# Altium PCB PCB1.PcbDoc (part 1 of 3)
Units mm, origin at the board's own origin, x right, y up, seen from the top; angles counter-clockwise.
Board outline 131.32 x 71.5 mm, 4 copper layers (Top Layer, Layer 1, Layer 2, Bottom Layer), stack 0.603 mm thick; 122 components, 132 nets, 671 pads, 444 vias.
Unrouted connection lines stored in the file: 1.
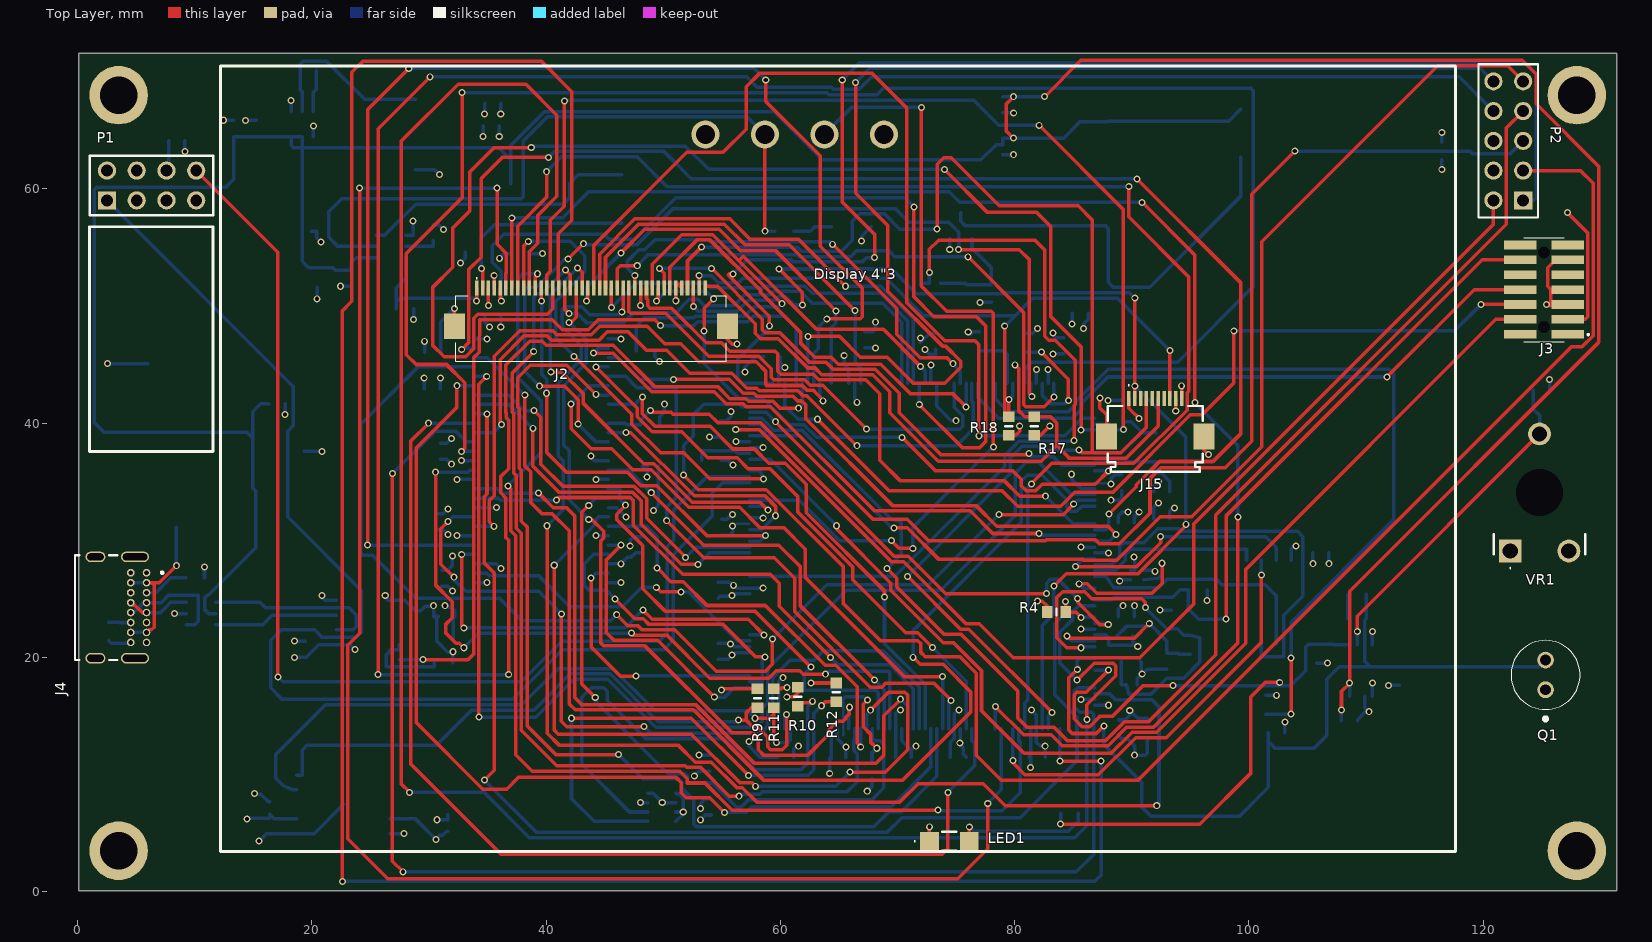
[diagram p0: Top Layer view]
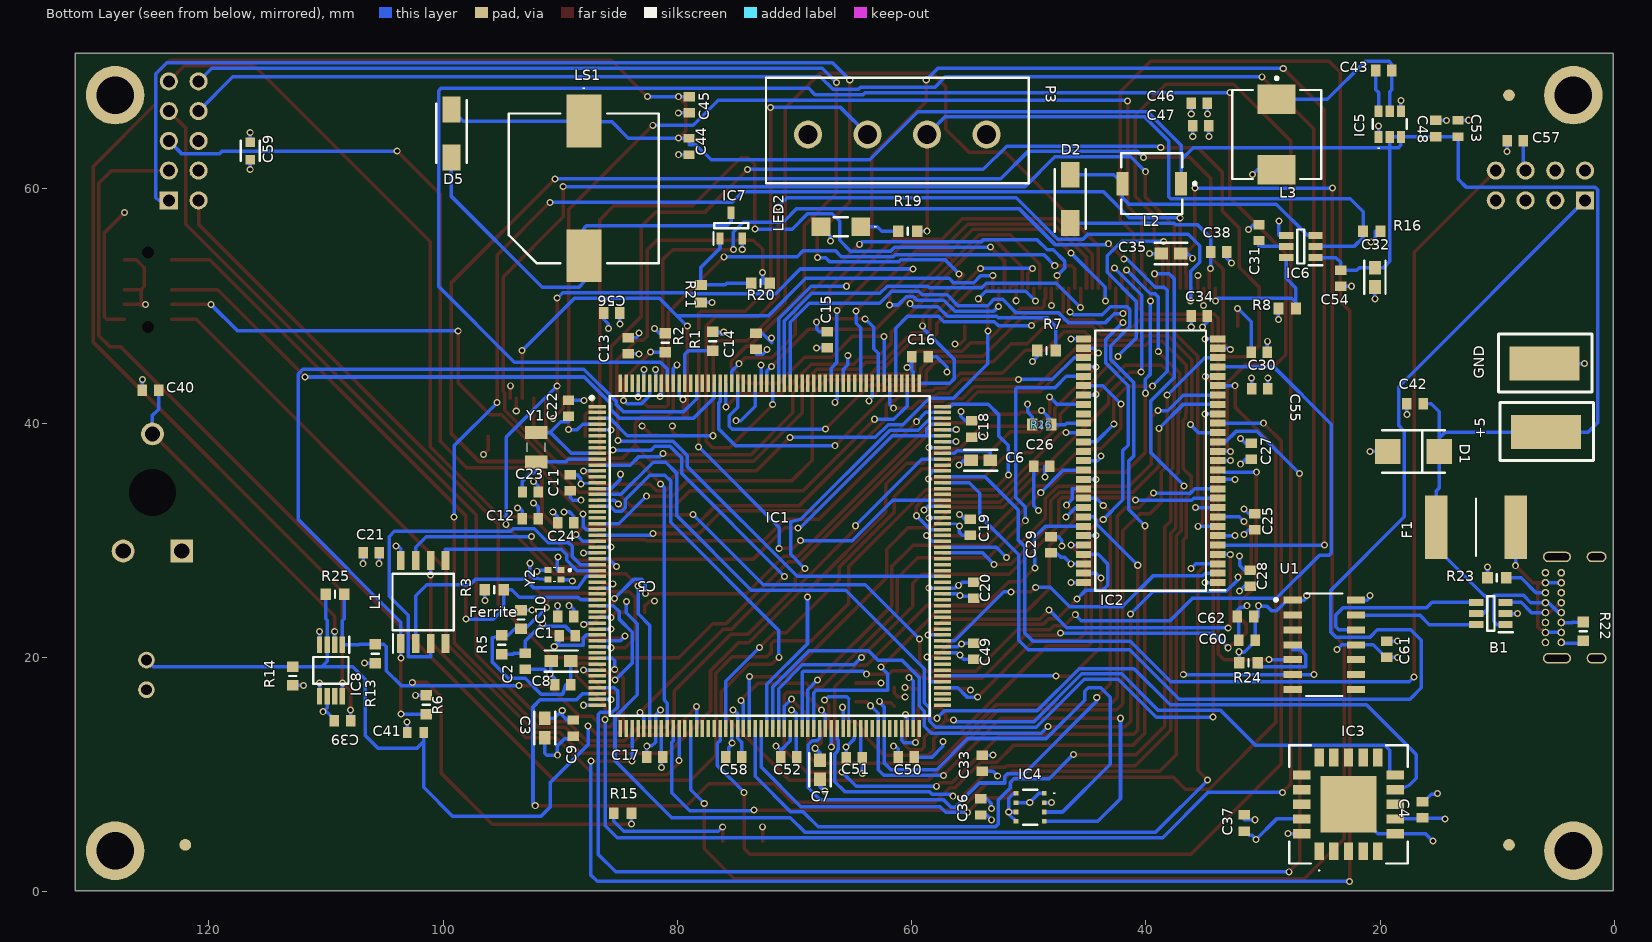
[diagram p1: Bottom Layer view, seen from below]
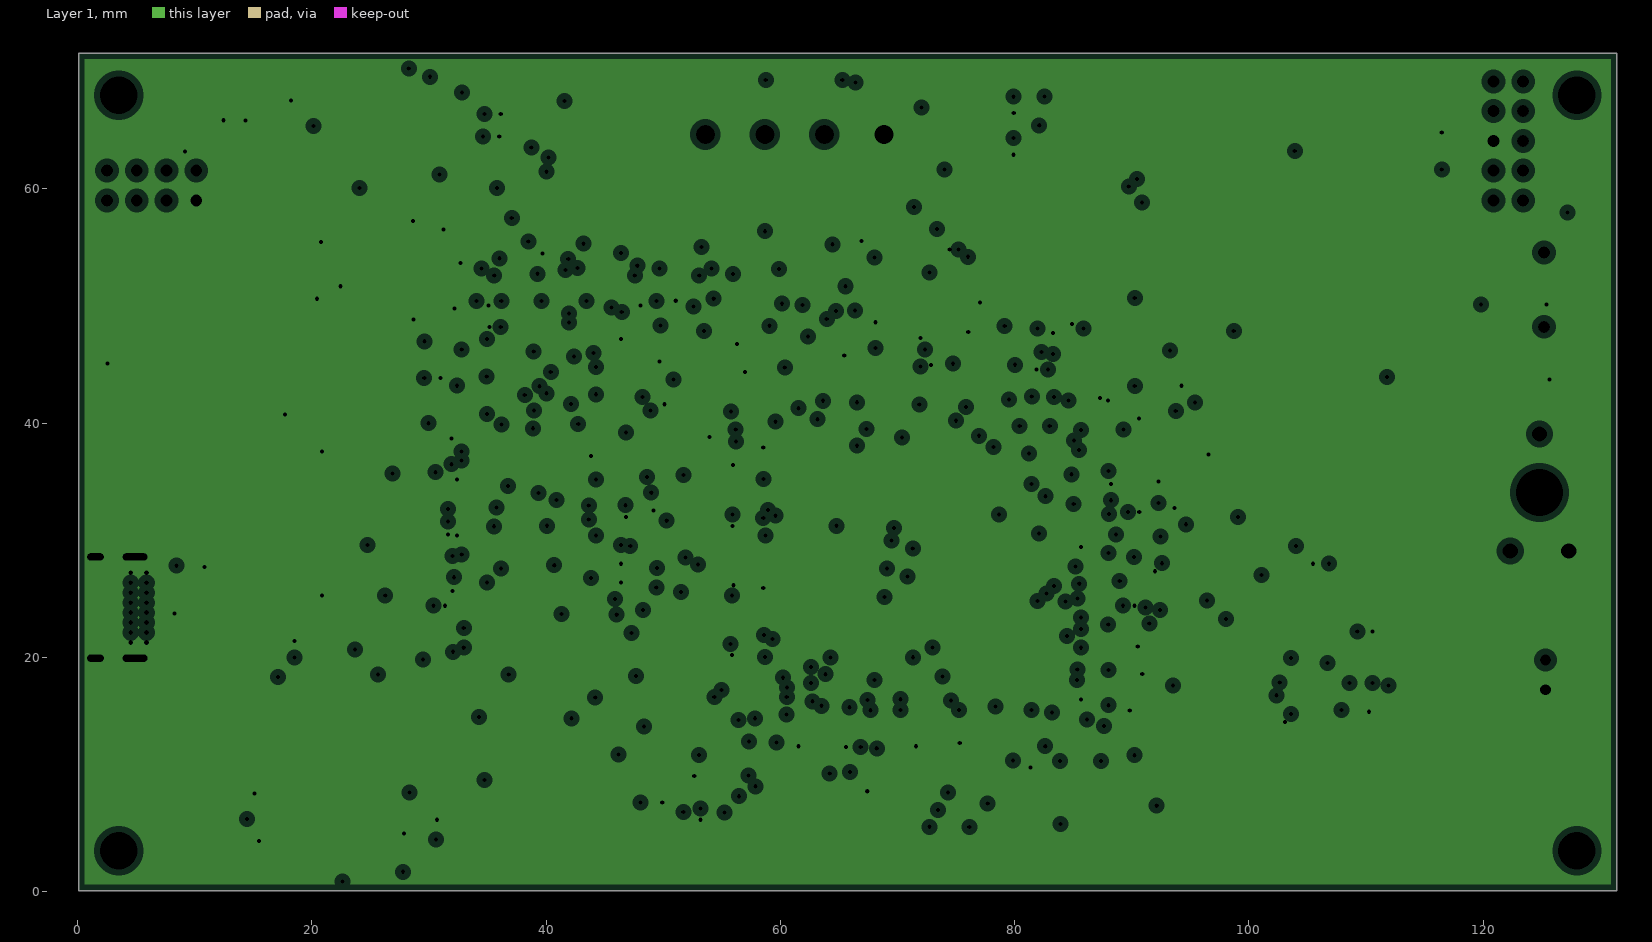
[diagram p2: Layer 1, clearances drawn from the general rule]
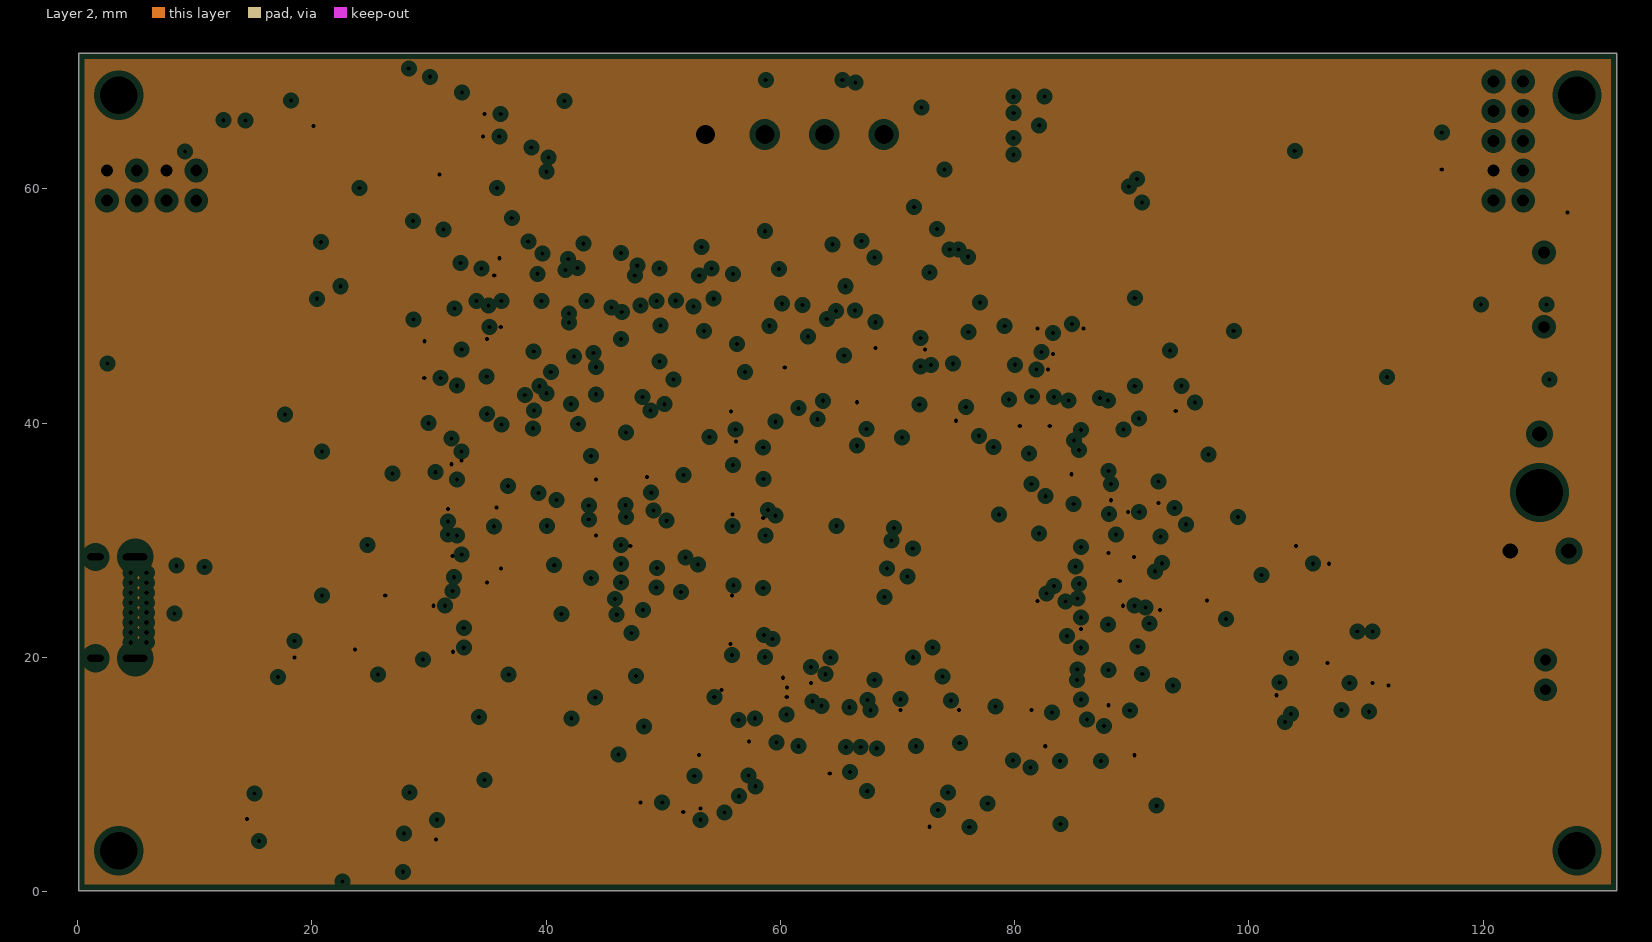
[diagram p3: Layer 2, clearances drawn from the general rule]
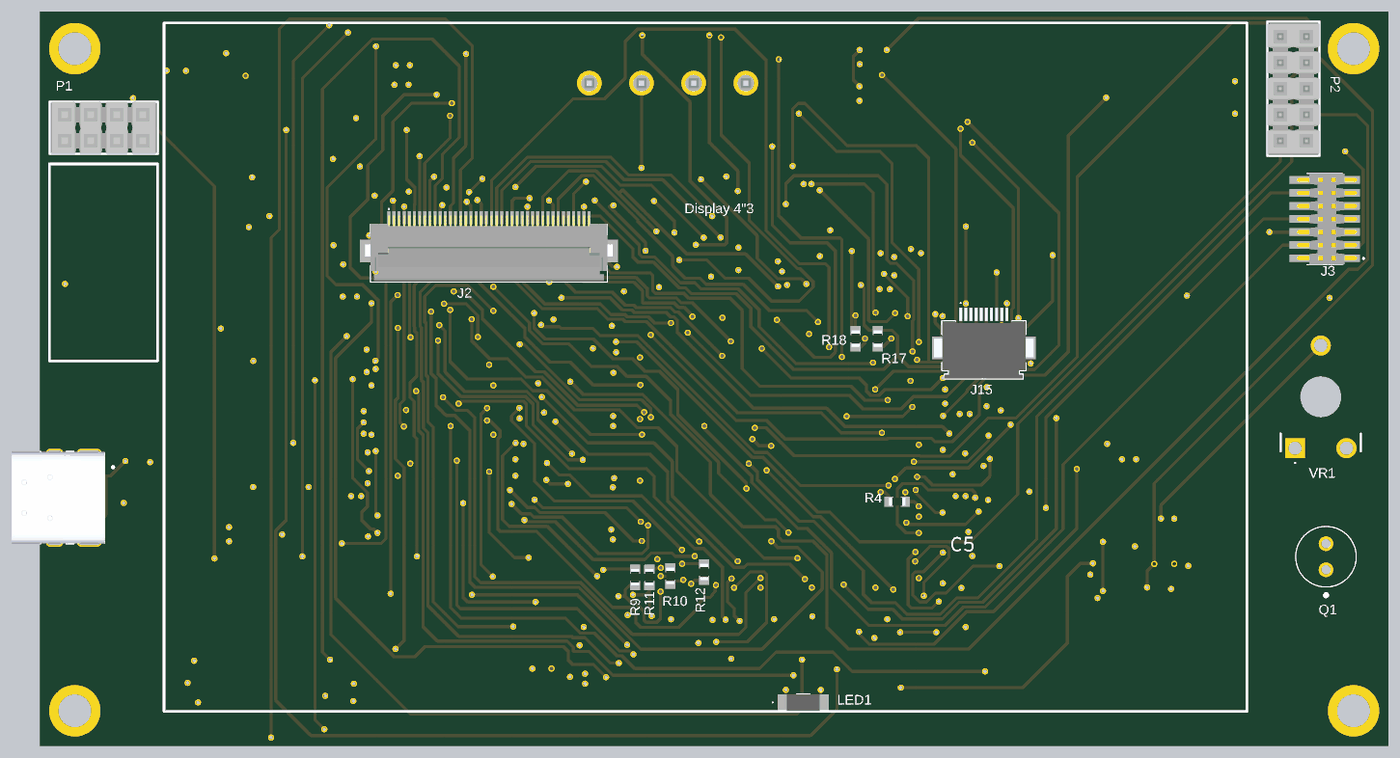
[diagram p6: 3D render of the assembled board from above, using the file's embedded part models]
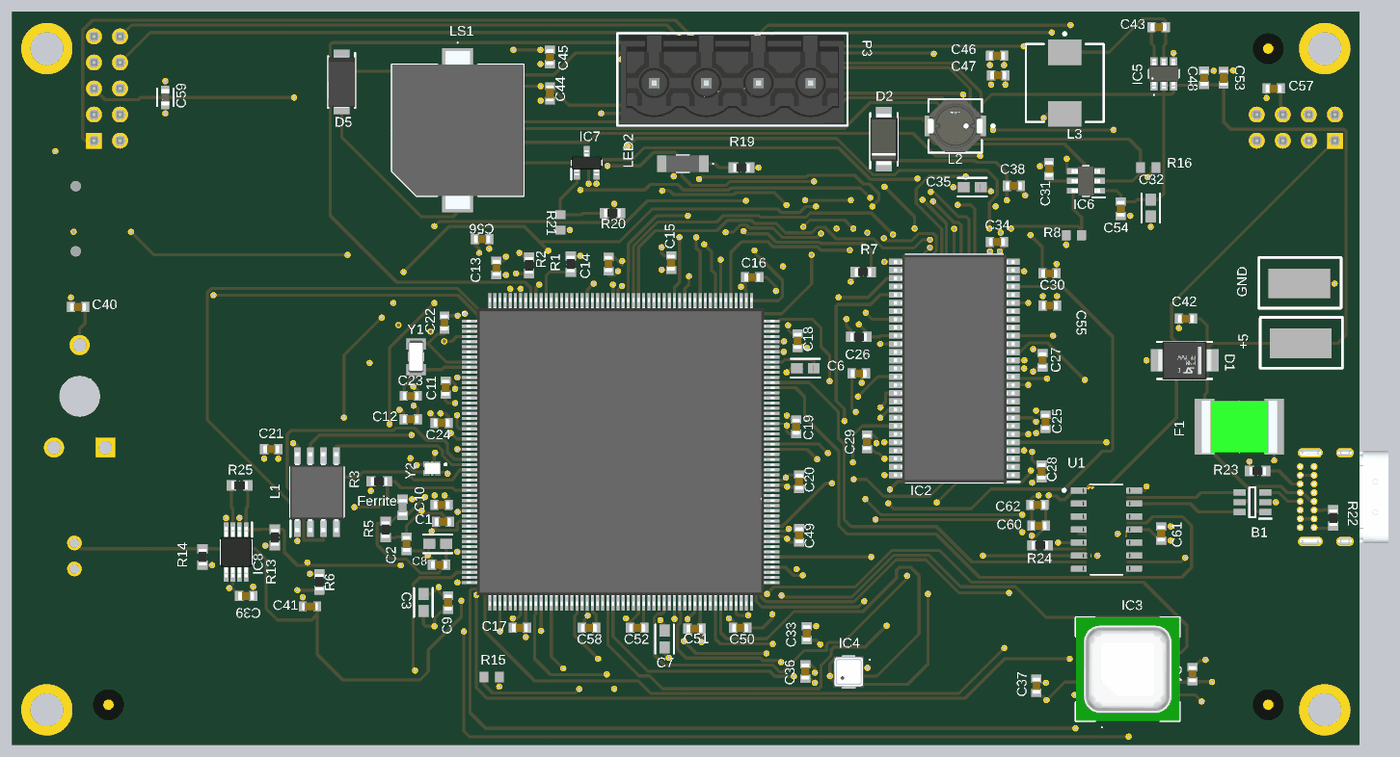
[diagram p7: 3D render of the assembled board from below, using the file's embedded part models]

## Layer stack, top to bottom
Top Solder: solder mask 0.0102, Solder Resist, Dk 3.5
Top Layer: signal copper 0.0356
Dielectric 2: prepreg 0.0711, PP-006, Dk 4.1
Layer 1: plane copper 0.035, net GND
Dielectric 1: dielectric 0.32, FR-4, Dk 4.8
Layer 2: plane copper 0.035, net 3V3
Dielectric 3: prepreg 0.0711, PP-006, Dk 4.1
Bottom Layer: signal copper 0.0356
Bottom Solder: solder mask 0.0102, Solder Resist, Dk 3.5

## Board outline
0.094,0.094 0.094,71.595 131.412,71.595 131.412,0.094

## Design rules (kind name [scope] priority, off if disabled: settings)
Clearance Clearance_OLTTTPPP [OnOutside] p1: gap=0.15 ignorepadtopadclearanceinfootprint=TRUE
Clearance Clearance_ILTTTPPP [All] p2: gap=0.15 ignorepadtopadclearanceinfootprint=TRUE except(0.2: Arc-Hole Track-Hole SMDPad-Hole THPad-Hole Via-Hole Fill-Hole Poly-Hole Region-Hole)
HoleSize [All] p1: absolutevalues=TRUE maxlimit=1000 minlimit=0.25 maxpercent=80.000 minpercent=20.000
HoleToHoleClearance HoleToHoleClearance_uVia_same_layer_inner [IsMicroVia and ((StartLayer = 'Inner 1') and (StopLayer = 'Inner 2')) vs IsMicroVia and ((StartLayer = 'Inner 1') and (StopLayer = 'Inner 2'))] p1: gap=0.2 allowstackedmicrovias=FALSE
HoleToHoleClearance HoleToHoleClearance_uVia_same_layer_top [IsMicroVia and ((StartLayer = 'Top Layer') and (StopLayer = 'Inner 1')) vs IsMicroVia and ((StartLayer = 'Top Layer') and (StopLayer = 'Inner 1'))] p2: gap=0.2 allowstackedmicrovias=FALSE
HoleToHoleClearance HoleToHoleClearance_uVia [IsMicroVia vs IsMicroVia] p3: gap=0.01 allowstackedmicrovias=FALSE
HoleToHoleClearance [All] p4: gap=0.2 allowstackedmicrovias=FALSE
MinimumAnnularRing MinimumAnnularRing_uVia [IsMicroVia] p1: minimumring=0.09
MinimumAnnularRing MinimumAnnularRing_OAR [OnOutside] p2: minimumring=0.125
MinimumAnnularRing MinimumAnnularRing_IAR [All] p3: minimumring=0.125
MinimumSolderMaskSliver [All] p1: minsoldermaskwidth=0.1
PlaneClearance [All] p1: clearance=0.508
PlaneConnect J4_GND_Direct [IsPad And InComponent('J4') And InNet('GND')] p1: planeconnectstyle=Direct reliefexpansion=0.508 reliefentries=4 reliefconductorwidth=0.254 reliefairgap=0.254
PlaneConnect [All] p2: planeconnectstyle=Relief reliefexpansion=0.508 reliefentries=4 reliefconductorwidth=0.254 reliefairgap=0.254
PolygonConnect [All] p1: connectstyle=Relief reliefconductorwidth=0.254 reliefentries=4 polygonreliefangle="90 Angle" airgapwidth=0.254
RoutingVias RoutingVias_uVia [IsMicroVia] p1: holewidth=0.1 width=0.28 viastyle="Through Hole" minholewidth=0.1 minwidth=0.28 maxholewidth=0.1 maxwidth=0.28
RoutingVias [All] p2: holewidth=0.35 width=0.6 viastyle="Through Hole" minholewidth=0.25 minwidth=0.5 maxholewidth=3 maxwidth=3.25
SilkToSolderMaskClearance [IsPad] p1: minsilkscreentomaskgap=0.15 clearancetoexposedcopper=TRUE
SolderMaskExpansion [All] p1: expansion=0 istentingtop=FALSE
SupplyNets "Schematic Supply Nets_4" [InNet('3V3')] p1: voltage=0.000
SupplyNets "Schematic Supply Nets_3" [InNet('+5')] p2: voltage=0.000
SupplyNets "Schematic Supply Nets_2" [InNet('VREF+')] p3: voltage=0.000
SupplyNets "Schematic Supply Nets_1" [InNet('VDDA')] p4: voltage=0.000
SupplyNets "Schematic Supply Nets" [InNet('GND')] p5: voltage=0.000
ViasUnderSMD [IsMicroVia] p1: allowed=TRUE
Width Width_ILTW [All] p1: maxlimit=3 minlimit=0.2 preferedwidth=0.3 minimp=50.000000 maximp=50.000000 favimp=50.000000
Width POWER [InNet('+5')] p2: maxlimit=3 minlimit=0.2 preferedwidth=0.5 minimp=50.000000 maximp=50.000000 favimp=50.000000
Width POWER_1 [InNet('3V3')] p3: maxlimit=3 minlimit=0.2 preferedwidth=0.5 minimp=50.000000 maximp=50.000000 favimp=50.000000
Width POWER_2 [InNet('GND')] p4: maxlimit=3 minlimit=0.2 preferedwidth=0.5 minimp=50.000000 maximp=50.000000 favimp=50.000000
24 further rules are at their usual default settings.

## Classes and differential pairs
component class Sheet2: +5 B1 C34 C42 C43 C46 C47 C48 C53 C60 C61 C62 D1 F1 GND IC5 J3 J4 L3 R22 R23 R24 U1
net class LCD_R[0..7]: LCD_R0 LCD_R1 LCD_R2 LCD_R3 LCD_R4 LCD_R5 LCD_R6 LCD_R7
net class LCD_G[0..7]: LCD_G0 LCD_G1 LCD_G2 LCD_G3 LCD_G4 LCD_G5 LCD_G6 LCD_G7
net class LCD_B[0..7]: LCD_B0 LCD_B1 LCD_B2 LCD_B3 LCD_B4 LCD_B5 LCD_B6 LCD_B7
net class SDRAM_D[0..15]: SDRAM_D0 SDRAM_D1 SDRAM_D2 SDRAM_D3 SDRAM_D4 SDRAM_D5 SDRAM_D6 SDRAM_D7 SDRAM_D8 SDRAM_D9 SDRAM_D10 SDRAM_D11 SDRAM_D12 SDRAM_D13 SDRAM_D14 SDRAM_D15
net class SDRAM_A[0..11]: SDRAM_A0 SDRAM_A1 SDRAM_A2 SDRAM_A3 SDRAM_A4 SDRAM_A5 SDRAM_A6 SDRAM_A7 SDRAM_A8 SDRAM_A9 SDRAM_A10 SDRAM_A11
component class Sheet6: C21 C22 C23 C24 C25 C26 C27 C28 C29 C30 C55 C57 C59 IC2 L1 P1 P2 R4 R6 R26 Y1 Y2
component class Sheet5: C31 C32 C35 C38 C54 C56 D2 IC6 J2 J15 L2 LED2 P3 R7 R8 R16 R17 R18 R19
component class Sheet3: C1 C2 C3 C5 C6 C7 C8 C9 C10 C11 C12 C13 C14 C15 C16 C17 C18 C19 C20 C49 C50 C51 C52 C58 Ferrite R5
component class Sheet4: C4 C33 C36 C37 C39 C40 C41 C44 C45 D5 IC3 IC4 IC7 IC8 LED1 LS1 Q1 R9 R10 R11 R12 R13 R14 R15 R20 R21 R25 VR1
component class Sheet1: IC1 R1 R2 R3

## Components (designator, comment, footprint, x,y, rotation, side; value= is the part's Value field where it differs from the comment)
+5 "1" ANT 6.096,39.624 r270 bottom
B1 "USBLC6-2SC6" SOT95P280X145-6N 10.541,23.749 r0 bottom
C1 "1uf" CAPC1608X95N 89.408,21.844 r180 bottom
C2 "100nf" CAPC1608X95N 92.964,19.685 r90 bottom
C3 "4.7uf" FP-CL10-IPC_A 91.313,13.97 r90 bottom
C4 "10Uf" CAPC1608X95N 16.383,6.985 r270 bottom
C5 "1UF" FP-CL10-IPC_A 89.916,19.685 r0 bottom
C6 "2.2uf" FP-CL10-IPC_A 54.102,36.83 r0 bottom
C7 "2.2uf" FP-CL10-IPC_A 67.818,10.414 r270 bottom
C8 "100nf" CAPC1608X95N 89.789,17.653 r180 bottom
C9 "100nf" CAPC1608X95N 88.9,13.97 r270 bottom
C10 "100nf" CAPC1608X95N 89.535,23.495 r180 bottom
C11 "100nf" CAPC1608X95N 89.154,34.925 r270 bottom
C12 "100nf" CAPC1608X95N 92.55,31.844 r180 bottom
C13 "100nf" CAPC1608X95N 84.201,46.609 r270 bottom
C14 "100nf" CAPC1608X95N 73.279,46.99 r270 bottom
C15 "100nf" CAPC1608X95N 67.183,47.117 r270 bottom
C16 "100nf" CAPC1608X95N 59.276,45.687 r0 bottom
C17 "100nf" CAPC1608X95N 81.915,11.5 r0 bottom
C18 "100nf" CAPC1608X95N 54.864,39.497 r90 bottom
C19 "100nf" CAPC1608X95N 54.991,31.115 r90 bottom
C20 "100nf" CAPC1608X95N 54.704,25.748 r270 bottom
C21 "100nf" CAPC1608X95N 106.139,28.923 r0 bottom
C22 "18pf" CAPC1608X87N 89.281,41.275 r270 bottom
C23 "18pf" CAPC1608X87N 92.55,34.13 r0 bottom
C24 "100nf" CAPC1608X95N 89.535,31.496 r180 bottom
C25 "100nf" CAPC1608X95N 30.701,31.59 r90 bottom
C26 "100nf" CAPC1608X95N 48.895,36.322 r180 bottom
C27 "100nf" CAPC1608X95N 30.988,37.592 r270 bottom
C28 "100nf" CAPC1608X95N 31.082,26.764 r90 bottom
C29 "100nf" CAPC1608X95N 48.1,29.634 r90 bottom
C30 "100nf" CAPC1608X95N 30.32,46.068 r180 bottom
C31 "220nF" CAPC1608X87N 30.353,56.261 r270 bottom
C32 "4.7uf" FP-CL10-IPC_A 20.447,52.451 r270 bottom
C33 "100nf" CAPC1608X95N 53.975,10.977 r90 bottom
C34 "100nf" CAPC1608X95N 35.433,49.149 r0 bottom
C35 "4.7uf" FP-CL10-IPC_A 37.846,54.483 r0 bottom
C36 "100nf" CAPC1608X95N 54.102,7.239 r90 bottom
C37 "100nf" CAPC1608X95N 31.59,5.86 r270 bottom
C38 "4.7uf" CAPC1608X95N 33.782,54.61 r0 bottom
C39 "100nf" CAPC1608X95N 108.585,14.605 r180 bottom
C40 "100nf" CAPC1608X95N 124.968,42.799 r180 bottom
C41 "0.47uf" CAPC1608X90N 102.362,13.589 r180 bottom
C42 "100nf" CAPC1608X95N 17.018,41.656 r180 bottom
C43 "100nf" CAPC1608X95N 19.685,70.104 r0 bottom
C44 "10uf" CAPC1608X90N 78.994,63.627 r90 bottom
C45 "100nf" CAPC1608X95N 78.994,67.183 r90 bottom
C46 "22uf" CAPC1608X95N 35.433,67.31 r180 bottom
C47 "22uf" CAPC1608X95N 35.306,65.405 r180 bottom
C48 "100nf" CAPC1608X95N 15.24,65.151 r270 bottom
C49 "100nf" CAPC1608X95N 54.704,20.541 r90 bottom
C50 "100nf" CAPC1608X95N 60.452,11.5 r180 bottom
C51 "100nf" CAPC1608X95N 64.897,11.43 r180 bottom
C52 "100nf" CAPC1608X95N 70.485,11.5 r180 bottom
C53 "10UF" CAPC1608X90N 13.335,65.151 r270 bottom
C54 "100nf" CAPC1608X95N 23.368,52.379 r90 bottom
C55 "4.7uf" CAPC1608X95N 30.281,42.926 r180 bottom
C56 "100nf" CAPC1608X95N 85.598,49.403 r0 bottom
C57 "100nf" CAPC1608X95N 8.476,64.102 r0 bottom
C58 "100nf" CAPC1608X95N 75.184,11.5 r180 bottom
C59 "100nf" FP-VJ0603X-MFG 116.459,63.246 r90 bottom
C60 "100nf" CAPC1608X95N 31.369,21.463 r180 bottom
C61 "330nf" CAPC1608X95N 19.431,20.701 r270 bottom
C62 "100nf" CAPC1608X95N 31.496,23.495 r180 bottom
D1 "SMBJ5.0A" SMBJ12A 17.145,37.592 r0 bottom
D2 "SS16-E3_61T" DIOM5127X229N 46.449,59.149 r90 bottom
D5 "SS14" DIOM5026X262N 99.281,64.737 r270 bottom
F1 "0ZCF0300BF2C" FUSC7451X115N 11.811,31.115 r0 bottom
Ferrite "FCM1608KF-601T03" BEADC1608X95N 93.345,23.241 r270 bottom (schematic designator "Ferrite Chip Bead")
GND "1" ANT 6.223,45.466 r270 bottom
IC1 "STM32F746BGT6" QFP50P3000X3000X160-208N 72.103,28.669 r180 bottom
IC2 "IS42S16400J-7TLI" SOP80P1176X120-54N 39.591,36.797 r0 bottom
IC3 "SCD41-D-R1" SCD41DR1 22.7,7.46 r90 bottom
IC4 "BME688" BME688 49.878,7.206 r180 bottom
IC5 "AP63203WU-7" AP63203WU7 19.177,65.532 r180 bottom
IC6 "TPS61165DBVT" SOT95P280X145-6N 26.764,55.085 r0 bottom
IC7 "2N7002P,235" SOT95P230X110-3N 75.405,56.863 r90 bottom
IC8 "LMV393MM_NOPB" SOP65P490X110-8N 109.568,18.89 r270 bottom
J2 "FH12-40S-0.5SH_55_" FH1240S05SH55 43.817,48.854 r0 top
J3 "FTSH-107-01-L-DV-K-A" FTSH-107-XX-YYY-DV-K-A 125.186,51.402 r90 top
J4 "USB4085-GF-A_REVA4" GCT_USB4085-GF-A_REVA4 1.524,24.257 r270 top
J15 "FH12-10S-0.5SH_55_" FH1210S05SH55 92,38.989 r0 top
L1 "W25Q128JVSIQ_TR" SOIC127P780X195-8N 101.694,24.732 r90 bottom
L2 "#A915AY-100M=P3" FP-D53LC-MFG 39.497,60.452 r0 bottom
L3 "DR74-4R7-R" COBU-DR74-4R7-R_V 28.829,64.643 r270 bottom
LED1 "KPTL-3216SURCK-01-VS" KPTL3216SURCK01VS 74.422,4.318 r0 top
LED2 "KPTL-3216SURCK-01-VS" KPTL3216SURCK01VS 66.04,56.769 r0 bottom
LS1 "SMI-1324-TW-5V-3-R" SMI1324TW5V3R 87.978,60.038 r90 bottom
P1 "ESP-01" SMTC-MTSW-104-12-X-D-006 2.507,59.022 r0 top
P2 "TSW-105-05-G-D" SMTC-TSW-105-05-X-D 123.411,59.022 r90 top
P3 "691701510004B" 691701510004B 61.214,64.993 r180 bottom
Q1 "PT334-6B" PT3346B 125.316,17.239 r90 top
R1 "10k" RESC1608X55N 76.962,46.99 r90 bottom
R2 "10k" RESC1608X55N 81.026,46.863 r270 bottom
R3 "10k" RESC1608X55N 95.631,25.781 r0 bottom
R4 "10k" RESC1608X55N 83.566,23.876 r0 top
R5 "47" RESC1608X55N 94.996,21.082 r90 bottom
R6 "10k" RESC1608X55N 101.44,15.969 r270 bottom
R7 "4k7" RESC1608X55N 48.481,46.195 r180 bottom
R8 "10 OHM" RESC1608X50N 27.94,49.784 r180 bottom
R9 "4k7" RESC1608X55N 58.039,16.51 r90 top
R10 "4k7" RESC1608X55N 61.468,16.637 r90 top
R11 "4k7" RESC1608X55N 59.436,16.51 r270 top
R12 "4k7" RESC1608X55N 64.77,17.018 r270 top
R13 "10k" RESC1608X55N 105.791,20.32 r90 bottom
R14 "10k" RESC1608X55N 112.838,18.415 r90 bottom
R15 "1k" RESC1608X50N 84.676,6.698 r0 bottom
R16 "100k" RESC1608X50N 20.701,56.388 r180 bottom
R17 "4k7" RESC1608X55N 81.661,39.751 r270 top
R18 "4k7" RESC1608X55N 79.502,39.751 r270 top
R19 "4k7" RESC1608X55N 60.325,56.388 r180 bottom
R20 "100 OHM" RESC1608X55N 72.898,51.943 r0 bottom
R21 "10K" RESC1608X50N 77.978,51.054 r90 bottom
R22 "5.1 kΩ, 1%" RESC1608X55N 2.667,22.225 r90 bottom
R23 "5.1 kΩ, 1%" RESC1608X55N 10.033,26.797 r180 bottom
R24 "10K" RESC1608X55N 31.242,19.558 r180 bottom
R25 "1M" RESC1608X55N 109.22,25.4 r0 bottom
R26 "10k" RESC1608X55N 48.895,39.878 r180 bottom
U1 "MCP2221A-I/SL" FP-C04-065-SL-MFG 24.765,21.082 r180 bottom
VR1 "PT10MV11-104A2020-S" PT10MV11104A2020S 122.308,29.083 r0 top
Y1 "ABS07-32.768KHZ-T" ABS07 92.042,37.94 r270 bottom
Y2 "ASCO-8.000MHZ-EK-T3" ASCO16000MHZEKT 90.17,27.051 r0 bottom

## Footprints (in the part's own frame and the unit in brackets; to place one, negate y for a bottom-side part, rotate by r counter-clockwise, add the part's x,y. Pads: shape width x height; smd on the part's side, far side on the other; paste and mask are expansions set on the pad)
691701510004B [mm] "THR - 5,08mm - PCB Vertical Close - 04p"
  round 2.4 hole 1.6: 1(-7.62,-0.35) 2(-2.54,-0.35) 3(2.54,-0.35) 4(7.62,-0.35)
  silkscreen extent -11.21,-4.5 11.21,4.5, body extent -10.86,-4.25 10.86,4.25, height 12.1
ABS07 [mm]
  rect 1.1x1.9 smd: 1(-1.25,0) 2(1.25,0)
  silkscreen extent -0.4,-0.75 0.4,0.75, body extent -1.6,-0.75 1.6,0.75, height 0.9
ANT [mm]
  rect 2.88x6 smd: 1(0.381,0.254)
  silkscreen extent -2.16,-3.68 2.79,4.32
AP63203WU7 [mm]
  rect 0.7x1 smd: 1(-0.95,-1.099) 2(0,-1.099) 3(0.95,-1.099) 4(0.95,1.099) 5(0,1.099) 6(-0.95,1.099)
  silkscreen extent -1.45,-2.1 1.45,0.4, body extent -1.45,-1.45 1.45,1.45, height 1
ASCO16000MHZEKT [mm]
  rect 0.6x0.5 smd: 1(-0.25,-0.4) 2(0.85,-0.4) 3(0.85,0.4) 4(-0.25,0.4)
  silkscreen extent -1.1,-0.6 0.4,0.6, body extent -0.52,-0.6 1.08,0.6, height 0.7
BEADC1608X95N [mm]
  rect 0.9x1 smd: 1(-0.8,0) 2(0.8,0)
  silkscreen extent 0,-0.3 0,0.3, body extent -0.8,-0.4 0.8,0.4, height 0.95
BME688 [mm]
  rect 0.4x0.4 smd: 1(1.2,1.2) 2(1.2,0.4) 3(1.2,-0.4) 4(1.2,-1.2) 5(-1.2,-1.2) 6(-1.2,-0.4) 7(-1.2,0.4) 8(-1.2,1.2)
  silkscreen extent -0.6,-1.5 2.1,1.5, body extent -1.5,-1.5 1.5,1.5, height 0.93
CAPC1608X87N [mm]
  rect 0.8x0.94 smd: 1(-0.67,0) 2(0.67,0)
  body extent -0.8,-0.4 0.8,0.4, height 0.87
CAPC1608X90N [mm]
  rect 0.73x0.94 smd: 1(-0.71,0) 2(0.71,0)
  body extent -0.8,-0.4 0.8,0.4, height 0.9
CAPC1608X95N [mm]
  rect 0.81x0.99 smd: 1(-0.69,0) 2(0.69,0)
  body extent -0.81,-0.41 0.81,0.41, height 0.95
COBU-DR74-4R7-R_V [mm] "SMD, 2-Leads, Body 7.6x7.6mm"
  rect 2.5x3.25 smd: 1(-3,0) 2(3,0)
  silkscreen extent -4.92,-3.8 3.8,3.8, body extent -3.8,-3.8 3.8,3.8, height 4.35
DIOM5026X262N [mm]
  rect 2.2x1.55 smd: 1(-2.05,0) 2(2.05,0)
  silkscreen extent -2.82,-1.31 2.52,1.31, body extent -2.52,-1.31 2.52,1.31, height 2.62
DIOM5127X229N [mm]
  rect 2.2x1.55 smd: 1(-2.05,0) 2(2.05,0)
  silkscreen extent -2.83,-1.33 2.55,1.33, body extent -2.55,-1.33 2.55,1.33, height 2.29
FH1210S05SH55 [mm]
  rect 0.3x1.3 smd: 1(-2.25,3.125) 2(-1.75,3.125) 3(-1.25,3.125) 4(-0.75,3.125) 5(-0.25,3.125) 6(0.25,3.125) 7(0.75,3.125) 8(1.25,3.125) 9(1.75,3.125) 10(2.25,3.125)
  rect 1.8x2.2 smd: 11(-4.15,-0.125) 12(4.15,-0.125)
  silkscreen extent -4.05,-3.13 4.05,4.3, body extent -4.87,-3.13 4.87,3.74, height 2.3
FH1240S05SH55 [mm]
  rect 0.3x1.3 smd: 1(-9.75,2.675) 2(-9.25,2.675) 3(-8.75,2.675) 4(-8.25,2.675) 5(-7.75,2.675) 6(-7.25,2.675) 7(-6.75,2.675) 8(-6.25,2.675) 9(-5.75,2.675) 10(-5.25,2.675) 11(-4.75,2.675) 12(-4.25,2.675) 13(-3.75,2.675) 14(-3.25,2.675) 15(-2.75,2.675) 16(-2.25,2.675) 17(-1.75,2.675) 18(-1.25,2.675) 19(-0.75,2.675) 20(-0.25,2.675) 21(0.25,2.675) 22(0.75,2.675) 23(1.25,2.675) 24(1.75,2.675) 25(2.25,2.675) 26(2.75,2.675) 27(3.25,2.675) 28(3.75,2.675) 29(4.25,2.675) 30(4.75,2.675) 31(5.25,2.675) 32(5.75,2.675) 33(6.25,2.675) 34(6.75,2.675) 35(7.25,2.675) 36(7.75,2.675) 37(8.25,2.675) 38(8.75,2.675) 39(9.25,2.675) 40(9.75,2.675)
  rect 1.8x2.2 smd: 41(-11.65,-0.575) 42(11.65,-0.575)
  silkscreen extent -11.55,-3.57 11.55,3.57, body extent -12.05,-3.52 12.05,2.88, height 2
FP-C04-065-SL-MFG [mm]
  rect 1.55x0.6 smd paste+0 mask+0: 1(-2.7,3.81) 2(-2.7,2.54) 3(-2.7,1.27) 4(-2.7,0) 5(-2.7,-1.27) 6(-2.7,-2.54) 7(-2.7,-3.81) 8(2.7,-3.81) 9(2.7,-2.54) 10(2.7,-1.27) 11(2.7,0) 12(2.7,1.27) 13(2.7,2.54) 14(2.7,3.81)
  silkscreen extent -4.25,-4.37 1.55,4.37, body extent -3,-4.33 3,4.33, height 1.75
FP-CL10-IPC_A [mm]
  rect 1.158x1.012 smd paste+0 mask+0: 1(-0.827,0) 2(0.827,0)
  silkscreen extent -1.41,-0.91 1.41,0.91, body extent -0.8,-0.4 0.8,0.4, height 0.9
FP-D53LC-MFG [mm]
  rect 1x2 smd paste+0 mask+0: 1(-2.5,0) 2(2.5,0)
  silkscreen extent -3.8,-2.6 2.6,2.6, body extent -2.7,-2.55 2.7,2.55, height 3
FP-VJ0603X-MFG [mm]
  rect 0.8x0.8 smd paste+0 mask+0: 1(-0.75,0) 2(0.75,0)
  silkscreen extent -0.85,-0.8 0.85,0.8, body extent -0.8,-0.4 0.8,0.4, height 0.95
FTSH-107-XX-YYY-DV-K-A [mm]
  rect 0.74x2.79 smd: 1(-3.81,-2.035) 2(-3.81,2.035) 3(-2.54,-2.035) 4(-2.54,2.035) 5(-1.27,-2.035) 6(-1.27,2.035) 7(0,-2.035) 8(0,2.035) 9(1.27,-2.035) 10(1.27,2.035) 11(2.54,-2.035) 12(2.54,2.035) 13(3.81,-2.035) 14(3.81,2.035)
  round 0.51 hole 1.02 unplated: 15(-3.175,0) 16(3.175,0)
  silkscreen extent -4.45,-3.83 4.44,1.72, body extent -4.44,-3.15 4.45,2.69, height 5.97
FUSC7451X115N [mm]
  rect 1.92x5.45 smd: 1(-3.385,0) 2(3.385,0)
  silkscreen extent 0,-2.46 0,2.46, body extent -3.68,-2.56 3.68,2.56, height 1.15
GCT_USB4085-GF-A_REVA4 [mm]
  round 0.65 hole 0.4: A1(-2.975,4.36) A4(-2.125,4.36) A5(-1.275,4.36) A6(-0.425,4.36) A7(0.425,4.36) A8(1.275,4.36) A9(2.125,4.36) A12(2.975,4.36) B1(2.975,3.01) B4(2.125,3.01) B5(1.275,3.01) B6(0.425,3.01) B7(-0.425,3.01) B8(-1.275,3.01) B9(-2.125,3.01) B12(-2.975,3.01)
  oval 0.9x1.7 hole 0.6 slot 1.4 at 90 deg: S1(-4.325,0) S2(4.325,0)
  oval 0.9x2.4 hole 0.6 slot 2.1 at 90 deg: S3(-4.325,3.38) S4(4.325,3.38)
  silkscreen extent -4.47,-1.74 4.47,5.8, body extent -4.47,-4.25 4.47,4.92, height 3.46
KPTL3216SURCK01VS [mm]
  rect 1.6x1.6 smd: 1(-1.7,0) 2(1.7,0)
  silkscreen extent -3,-0.8 0.6,0.8, body extent -1.6,-0.8 1.6,0.8, height 1.3
PT10MV11104A2020S [mm]
  rect 1.95x1.95 hole 1.3: A1(0,0)
  round 1.95 hole 1.3: E1(5,0) S1(2.5,10)
  round 2 hole 4 unplated: MH1(2.5,5)
  silkscreen extent -1.4,-1.5 6.4,1.42
PT3346B [mm]
  round 1.42 hole 0.92: 1(0,0) 2(2.54,0)
  silkscreen extent -2.63,-2.95 4.22,2.95
QFP50P3000X3000X160-208N [mm]
  rect 1.475x0.3 smd: 1(-14.738,12.75) 2(-14.738,12.25) 3(-14.738,11.75) 4(-14.738,11.25) 5(-14.738,10.75) 6(-14.738,10.25) 7(-14.738,9.75) 8(-14.738,9.25) 9(-14.738,8.75) 10(-14.738,8.25) 11(-14.738,7.75) 12(-14.738,7.25) 13(-14.738,6.75) 14(-14.738,6.25) 15(-14.738,5.75) 16(-14.738,5.25) 17(-14.738,4.75) 18(-14.738,4.25) 19(-14.738,3.75) 20(-14.738,3.25) 21(-14.738,2.75) 22(-14.738,2.25) 23(-14.738,1.75) 24(-14.738,1.25) 25(-14.738,0.75) 26(-14.738,0.25) 27(-14.738,-0.25) 28(-14.738,-0.75) 29(-14.738,-1.25) 30(-14.738,-1.75) 31(-14.738,-2.25) 32(-14.738,-2.75) 33(-14.738,-3.25) 34(-14.738,-3.75) 35(-14.738,-4.25) 36(-14.738,-4.75) 37(-14.738,-5.25) 38(-14.738,-5.75) 39(-14.738,-6.25) 40(-14.738,-6.75) 41(-14.738,-7.25) 42(-14.738,-7.75) 43(-14.738,-8.25) 44(-14.738,-8.75) 45(-14.738,-9.25) 46(-14.738,-9.75) 47(-14.738,-10.25) 48(-14.738,-10.75) 49(-14.738,-11.25) 50(-14.738,-11.75) 51(-14.738,-12.25) 52(-14.738,-12.75) 105(14.738,-12.75) 106(14.738,-12.25) 107(14.738,-11.75) 108(14.738,-11.25) 109(14.738,-10.75) 110(14.738,-10.25) 111(14.738,-9.75) 112(14.738,-9.25) 113(14.738,-8.75) 114(14.738,-8.25) 115(14.738,-7.75) 116(14.738,-7.25) 117(14.738,-6.75) 118(14.738,-6.25) 119(14.738,-5.75) 120(14.738,-5.25) 121(14.738,-4.75) 122(14.738,-4.25) 123(14.738,-3.75) 124(14.738,-3.25) 125(14.738,-2.75) 126(14.738,-2.25) 127(14.738,-1.75) 128(14.738,-1.25) 129(14.738,-0.75) 130(14.738,-0.25) 131(14.738,0.25) 132(14.738,0.75) 133(14.738,1.25) 134(14.738,1.75) 135(14.738,2.25) 136(14.738,2.75) 137(14.738,3.25) 138(14.738,3.75) 139(14.738,4.25) 140(14.738,4.75) 141(14.738,5.25) 142(14.738,5.75) 143(14.738,6.25) 144(14.738,6.75) 145(14.738,7.25) 146(14.738,7.75) 147(14.738,8.25) 148(14.738,8.75) 149(14.738,9.25) 150(14.738,9.75) 151(14.738,10.25) 152(14.738,10.75) 153(14.738,11.25) 154(14.738,11.75) 155(14.738,12.25) 156(14.738,12.75)
  rect 0.3x1.475 smd: 53(-12.75,-14.738) 54(-12.25,-14.738) 55(-11.75,-14.738) 56(-11.25,-14.738) 57(-10.75,-14.738) 58(-10.25,-14.738) 59(-9.75,-14.738) 60(-9.25,-14.738) 61(-8.75,-14.738) 62(-8.25,-14.738) 63(-7.75,-14.738) 64(-7.25,-14.738) 65(-6.75,-14.738) 66(-6.25,-14.738) 67(-5.75,-14.738) 68(-5.25,-14.738) 69(-4.75,-14.738) 70(-4.25,-14.738) 71(-3.75,-14.738) 72(-3.25,-14.738) 73(-2.75,-14.738) 74(-2.25,-14.738) 75(-1.75,-14.738) 76(-1.25,-14.738) 77(-0.75,-14.738) 78(-0.25,-14.738) 79(0.25,-14.738) 80(0.75,-14.738) 81(1.25,-14.738) 82(1.75,-14.738) 83(2.25,-14.738) 84(2.75,-14.738) 85(3.25,-14.738) 86(3.75,-14.738) 87(4.25,-14.738) 88(4.75,-14.738) 89(5.25,-14.738) 90(5.75,-14.738) 91(6.25,-14.738) 92(6.75,-14.738) 93(7.25,-14.738) 94(7.75,-14.738) 95(8.25,-14.738) 96(8.75,-14.738) 97(9.25,-14.738) 98(9.75,-14.738) 99(10.25,-14.738) 100(10.75,-14.738) 101(11.25,-14.738) 102(11.75,-14.738) 103(12.25,-14.738) 104(12.75,-14.738) 157(12.75,14.738) 158(12.25,14.738) 159(11.75,14.738) 160(11.25,14.738) 161(10.75,14.738) 162(10.25,14.738) 163(9.75,14.738) 164(9.25,14.738) 165(8.75,14.738) 166(8.25,14.738) 167(7.75,14.738) 168(7.25,14.738) 169(6.75,14.738) 170(6.25,14.738) 171(5.75,14.738) 172(5.25,14.738) 173(4.75,14.738) 174(4.25,14.738) 175(3.75,14.738) 176(3.25,14.738) 177(2.75,14.738) 178(2.25,14.738) 179(1.75,14.738) 180(1.25,14.738) 181(0.75,14.738) 182(0.25,14.738) 183(-0.25,14.738) 184(-0.75,14.738) 185(-1.25,14.738) 186(-1.75,14.738) 187(-2.25,14.738) 188(-2.75,14.738) 189(-3.25,14.738) 190(-3.75,14.738) 191(-4.25,14.738) 192(-4.75,14.738) 193(-5.25,14.738) 194(-5.75,14.738) 195(-6.25,14.738) 196(-6.75,14.738) 197(-7.25,14.738) 198(-7.75,14.738) 199(-8.25,14.738) 200(-8.75,14.738) 201(-9.25,14.738) 202(-9.75,14.738) 203(-10.25,14.738) 204(-10.75,14.738) 205(-11.25,14.738) 206(-11.75,14.738) 207(-12.25,14.738) 208(-12.75,14.738)
  silkscreen extent -15.35,-13.65 13.65,13.65, body extent -15,-15 15,15, height 1.6
RESC1608X50N [mm]
  rect 0.85x1 smd: 1(-0.75,0) 2(0.75,0)
RESC1608X55N [mm]
  rect 0.9x1 smd: 1(-0.8,0) 2(0.8,0)
  silkscreen extent 0,-0.3 0,0.3, body extent -0.8,-0.4 0.8,0.4, height 0.55
SCD41DR1 [mm]
  rect 1.5x0.8 smd: 1(-4,2.5) 2(-4,1.25) 3(-4,0) 4(-4,-1.25) 5(-4,-2.5) 11(4,-2.5) 12(4,-1.25) 13(4,0) 14(4,1.25) 15(4,2.5)
  rect 0.8x1.5 smd: 6(-2.5,-4) 7(-1.25,-4) 8(0,-4) 9(1.25,-4) 10(2.5,-4) 16(2.5,4) 17(1.25,4) 18(0,4) 19(-1.25,4) 20(-2.5,4)
  rect 4.8x4.8 smd: 21(0,0)
  silkscreen extent -5.7,-5.05 5.05,5.05, body extent -5.05,-5.05 5.05,5.05, height 6.31
SMBJ12A [mm]
  rect 2.2x2.15 smd: 1(-2.2,0) 2(2.2,0)
  silkscreen extent -2.67,-1.81 2.68,1.81, body extent -2.68,-1.86 2.68,1.86, height 2.33
SMI1324TW5V3R [mm]
  rect 4.5x3 smd: 1(5.75,0) 2(-5.75,0)
  silkscreen extent -6.4,-6.4 8.6,6.4, body extent -7.7,-6.4 7.7,6.4, height 7.6
SMTC-MTSW-104-12-X-D-006 [mm] "Assembly .025\" [.64] SQ Post Terminal Strip, 2x4 Pins, Vertical, 2.54mm Pitch, Male"
  rect 1.55x1.55 hole 1.02: 1(0,0)
  round 1.55 hole 1.02: 2(0,2.54) 3(2.54,0) 4(2.54,2.54) 5(5.08,0) 6(5.08,2.54) 7(7.62,0) 8(7.62,2.54)
  silkscreen extent -1.46,-1.27 9.08,3.81, body extent -1.27,-1.27 8.89,3.81, height 2.69
SMTC-TSW-105-05-X-D [mm] ".025 SQ Post Terminal Strip Assembly, 2x5 Pins, Vertical, 2.54mm Pitch, Male"
  rect 1.55x1.55 hole 1.02: 1(0,0)
  round 1.55 hole 1.02: 2(0,2.54) 3(2.54,0) 4(2.54,2.54) 5(5.08,0) 6(5.08,2.54) 7(7.62,0) 8(7.62,2.54) 9(10.16,0) 10(10.16,2.54)
  silkscreen extent -1.46,-1.27 11.62,3.81, body extent -1.27,-1.27 11.43,3.81, height 5.21
SOIC127P780X195-8N [mm]
  rect 1.6x0.65 smd: 1(-3.55,1.905) 2(-3.55,0.635) 3(-3.55,-0.635) 4(-3.55,-1.905) 5(3.55,-1.905) 6(3.55,-0.635) 7(3.55,0.635) 8(3.55,1.905)
  silkscreen extent -4.35,-2.62 2.4,2.61, body extent -3.9,-2.62 3.9,2.62, height 1.95
SOP65P490X110-8N [mm]
  rect 1.4x0.45 smd: 1(-2.2,0.975) 2(-2.2,0.325) 3(-2.2,-0.325) 4(-2.2,-0.975) 5(2.2,-0.975) 6(2.2,-0.325) 7(2.2,0.325) 8(2.2,0.975)
  silkscreen extent -2.9,-1.5 1.15,1.55, body extent -2.45,-1.5 2.45,1.5, height 1.1
SOP80P1176X120-54N [mm]
  rect 1.295x0.6 smd: 1(-5.728,10.4) 2(-5.728,9.6) 3(-5.728,8.8) 4(-5.728,8) 5(-5.728,7.2) 6(-5.728,6.4) 7(-5.728,5.6) 8(-5.728,4.8) 9(-5.728,4) 10(-5.728,3.2) 11(-5.728,2.4) 12(-5.728,1.6) 13(-5.728,0.8) 14(-5.728,0) 15(-5.728,-0.8) 16(-5.728,-1.6) 17(-5.728,-2.4) 18(-5.728,-3.2) 19(-5.728,-4) 20(-5.728,-4.8) 21(-5.728,-5.6) 22(-5.728,-6.4) 23(-5.728,-7.2) 24(-5.728,-8) 25(-5.728,-8.8) 26(-5.728,-9.6) 27(-5.728,-10.4) 28(5.728,-10.4) 29(5.728,-9.6) 30(5.728,-8.8) 31(5.728,-8) 32(5.728,-7.2) 33(5.728,-6.4) 34(5.728,-5.6) 35(5.728,-4.8) 36(5.728,-4) 37(5.728,-3.2) 38(5.728,-2.4) 39(5.728,-1.6) 40(5.728,-0.8) 41(5.728,0) 42(5.728,0.8) 43(5.728,1.6) 44(5.728,2.4) 45(5.728,3.2) 46(5.728,4) 47(5.728,4.8) 48(5.728,5.6) 49(5.728,6.4) 50(5.728,7.2) 51(5.728,8) 52(5.728,8.8) 53(5.728,9.6) 54(5.728,10.4)
  silkscreen extent -6.38,-11.11 4.73,11.11, body extent -5.88,-11.11 5.88,11.11, height 1.2
SOT95P230X110-3N [mm]
  rect 1.05x0.6 smd: 1(-1.1,0.95) 2(-1.1,-0.95) 3(1.1,0)
  silkscreen extent -1.63,-1.45 0.22,1.5, body extent -1.2,-1.45 1.2,1.45, height 0.95
SOT95P280X145-6N [mm]
  rect 1.2x0.6 smd: 1(-1.25,0.95) 2(-1.25,0) 3(-1.25,-0.95) 4(1.25,-0.95) 5(1.25,0) 6(1.25,0.95)
  silkscreen extent -1.85,-1.46 0.3,1.6

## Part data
B1: "TVS Diode Array Uni-Directional USBLC6-2SC6 17V, SOT-23 6-Pin", Manufacturer_Name=STMicroelectronics, Mouser Part Number=511-USBLC6-2SC6
C1 C38: library part 0603X105K250CT, "WALSIN - 0603X105K250CT - SMD Multilayer Ceramic Capacitor, 1 F, 25 V, 0603 [1608 Metric], +/- 10%, X5R", Manufacturer_Name="Walsin Technology Corporation"
C2 C4 C8 C9 C10 C11 C12 C13 C14 C15 C16 C17 C18 C19 C20 C21 C24 C25 C26 C27 C28 C29 C30 C33 C34 C36 C37 C39 C40 C42 C43 C45 C46 C47 C48 C49 C50 C51 C52 C54 C55 C56 C57 C58 C60 C61 C62: library part VJ0603Y104KXACW1BC, "Capacitor", Manufacturer_Name=Vishay, Mouser Part Number=N/A
C3 C5 C6 C7 C32 C35: library part CMP-13271-003582-1, "Cap Ceramic 2.2uF 10V X7R ±10% Pad SMD 0603 +125°C T/R", Capacitance=2.2uF, Case Code (Imperial)=0603, Case Code (Metric)=1608, Dielectric=X7R, Max Operating Temperature=125°C, Min Operating Temperature=-55°C, Package Quantity=1, Tolerance=10%, Voltage Rating=10V
C22 C23: library part C0603C180J5GAC, "Multilayer Ceramic Capacitors MLCC - SMD/SMT 50volts 18pF 5% C0G", Manufacturer_Name=KEMET, Mouser Part Number=80-C0603C180J5GAC
C31: library part 0603B223K500CT, "WALSIN - 0603B223K500CT - CAPACITOR, MLCC, X7R, 0.022UF, 50V, 0603", Manufacturer_Name="Walsin Technology Corporation", Mouser Part Number=791-0603B223K500CT
C41: library part CC0603KRX7R6BB474, "Phycomp 0603 Standard 470nF Ceramic Multilayer Capacitor, 10 V dc, +125C, X7R Dielectric, +/-10% SMD", Manufacturer_Name=KEMET, Mouser Part Number=603-CC603KRX7R6BB474
C44 C53: library part CL10A106KP8NNNC, "10F +/-10% 10V Ceramic Capacitor X5R 0603 (1608 Metric)", Manufacturer_Name=SAMSUNG, Mouser Part Number=187-CL10A106KP8NNNC
C59: library part CMP-02417-000051-1, "CAP CER 0.1UF 50V X7R 0603", Capacitance=100nF, Case Code (Imperial)=0603, Case Code (Metric)=1608, Dielectric=X7R, Dielectric Material=Tantalum, Max Operating Temperature=125°C, Min Operating Temperature=-55°C, Tolerance=10%, Voltage=50V
D1: "TVS Diode (Uni-directional)", Manufacturer_Name=STMicroelectronics
D2: "Diode", Arrow Part Number=SS16-E3/61T, Manufacturer_Name=Vishay, Mouser Part Number=625-SS16-E3
D5: "Battery", Manufacturer_Name="HY Electronic"
F1: "Fuse", Manufacturer_Name=BelFuse, Mouser Part Number=530-0ZCF0300BF2C
Ferrite: "Ferrite Bead", Manufacturer_Name=TAI-TECH
IC1: "Integrated Circuit", Manufacturer_Name=STMicroelectronics, Mouser Part Number=511-STM32F746BGT6
IC2: "Integrated Circuit", Manufacturer_Name="Integrated Silicon Solution Inc.", Mouser Part Number=870-IS42S16400J-7TLI
IC3: "Integrated Circuit", Manufacturer_Name=Sensirion, Mouser Part Number=403-SCD41-D-R1
IC4: "Integrated Circuit", Manufacturer_Name=BOSCH, Mouser Part Number=262-BME688
IC5: "Integrated Circuit", Manufacturer_Name="Diodes Incorporated", Mouser Part Number=621-AP63203WU-7
IC6: "Integrated Circuit", Manufacturer_Name="Texas Instruments", Mouser Part Number=595-TPS61165DBVT
IC7: "Integrated Circuit", Manufacturer_Name=Nylofix
IC8: "Integrated Circuit", Arrow Part Number=LMV393MM/NOPB, Manufacturer_Name="Texas Instruments", Mouser Part Number=926-LMV393MM/NOPB
J2: "Connector", Arrow Part Number=FH12-40S-0.5SH(55), Manufacturer_Name=Hirose, Mouser Part Number=798-FH12-40S-0.5SH55
J3: "Connector", Manufacturer_Name=SAMTEC, Mouser Part Number=200-FTSH10701LDVKA
J4: "USB-C (USB TYPE-C) USB 2.0 Receptacle Connector 24 (16+8 Dummy) Position Through Hole, Right Angle, low cost, 3.46mm profile, 16 pin, horizontal, Top mount", Package=None
J15: "Connector", Arrow Part Number=FH12-10S-0.5SH(55), Manufacturer_Name=Hirose, Mouser Part Number=798-FH12-10S-0.5SH55
L1: "Inductor", Arrow Part Number="W25Q128JVSIQ TR", Manufacturer_Name=Winbond, Mouser Part Number=454-W25Q128JVSIQTR
L2: library part CMP-06042-000140-1, "FIXED IND 10UH 1.49A 90 MOHM SMD", Case/Package=2020, Tolerance=20%
L3: library part CMP-2000-06180-1, "High Power Density, High Efficiency, Shielded Inductor, 4.7 uH, -40 to 125 degC, RoHS, Tape and Reel", Current - Saturation=4.37A, Current Rating=3.34A, DC Resistance (DCR)=25.4mOhm, Frequency - Self Resonant=-, Frequency - Test=100kHz, Inductance=4.7µH, Manufacturer=Eaton, Operating Temperature=-40°C~125°C, Package / Case=Nonstandard, Package Description="2-Pin Surface Mount Device, Body 7.6 x 7.6 mm", Tolerance=±20%
LED1 LED2: "LED", Manufacturer_Name=Kingbright, Mouser Part Number=N/A
LS1: "Loudspeaker or Buzzer", Manufacturer_Name="PUI Audio", Mouser Part Number=665-SMI1324TW5V3R
P1: library part CMP-1024-00110-1, "Modified .025\" SQ Post Header, Through-hole, Vertical, -55 to 105 degC, 2.54 mm Pitch, 8-Pin, Male, RoHS", Manufacturer=Samtec, PartNumber=MTSW-104-12-T-D-006, Temperature Range="-55 to 105 degC"
P2: library part CMP-1024-00362-1, "0.025\" SQ Post Header, Through-hole, Vertical, -55 to 125 degC, 2.54 mm Pitch, 10-Pin, Male, RoHS", Manufacturer=Samtec, Temperature Range="-55 to 125 degC"
P3: library part CMP-1502-02331-3, "Terminal Block, 5.08MM, Close Vertical Pcb Header, Thr Type, 4 Pins", Color=Black, Current Rating=10A, Max Operating Temperature=105°C, Min Operating Temperature=-40°C, Voltage Rating=300V
Q1: "Phototransistor", Manufacturer_Name=Everlight, Mouser Part Number=638-PT3346B
R1 R2 R3 R4 R5 R6 R13 R14 R22 R23 R24 R25 R26: library part RC0603FR-071KL, "Resistor", Manufacturer_Name=YAGEO, Mouser Part Number=603-RC0603FR-071KL
R7 R9 R10 R11 R12 R17 R18 R19: library part CRCW06034K70JNEAC, "Resistor", Manufacturer_Name=Vishay, Mouser Part Number=71-CRCW06034K70JNEAC
R8: library part RCA0603100KFKEA, "AR03BTCX6R80", Manufacturer_Name=Vishay, Mouser Part Number=71-RCA0603100KFKEA
R15: library part CRCW06031K00FKEA, "CRCW0603 Resistor T/R 0.10W,1%,1K Vishay CRCW Series Thick Film Surface Mount Resistor 0603 Case 1k +/-1% 0.1W +/-100ppm/C", Manufacturer_Name=Vishay, Mouser Part Number=71-CRCW0603-1.0K-E3
R16 R21: library part RCA0603100KFKEA, "100 kOhms +/-1% 0.1W, 1/10W Chip Resistor 0603 (1608 Metric) Anti-Sulfur, Automotive AEC-Q200 Thick Film", Manufacturer_Name=Vishay, Mouser Part Number=71-RCA0603100KFKEA
R20: library part TNPW0603100RFHEA, "Res Thin Film 0603 100 Ohm 1% 0.1W(1/10W) +/-50ppm/C Sulfur Resistant Pad SMD Automotive Medical T/R", Manufacturer_Name=Vishay
U1: library part CMP-06284-000011-1, "IC USB TO I2C/UART 14SOIC", Ambient Temperature Range High=+85°C, Ambient Temperature Range Low=-40°C, Manufacturer=Microchip, Max Junction Temp=+150°C, Max Supply Voltage=5.5V, Min Supply Voltage=3V, Nominal Supply Current=10-13mA, Package=C04-065-SL, Temperature="-40°C to +85°C"
VR1: "Variable Resistor", Manufacturer_Name=PIHER, Mouser Part Number=531-PT10MV11104A22S
Y1: "Crystal or Oscillator", Manufacturer_Name=ABRACON, Mouser Part Number=815-ABS07-32.768KHZT
Y2: "Crystal or Oscillator", Manufacturer_Name=ABRACON, Mouser Part Number=815-ASCO-8-EK-T3

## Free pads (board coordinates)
  round 5 hole 3.2 unplated paste-2539.97: 13(3.5,3.5) 13(3.5,68) 13(128,3.5) 13(128,68)
  round 1 smd far side paste-2539.97 mask+1: 14(9,4) 14(9,68) 14(122,4)

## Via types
v1: diameter 0.6, hole 0.35, Top Layer to Bottom Layer, 444 vias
